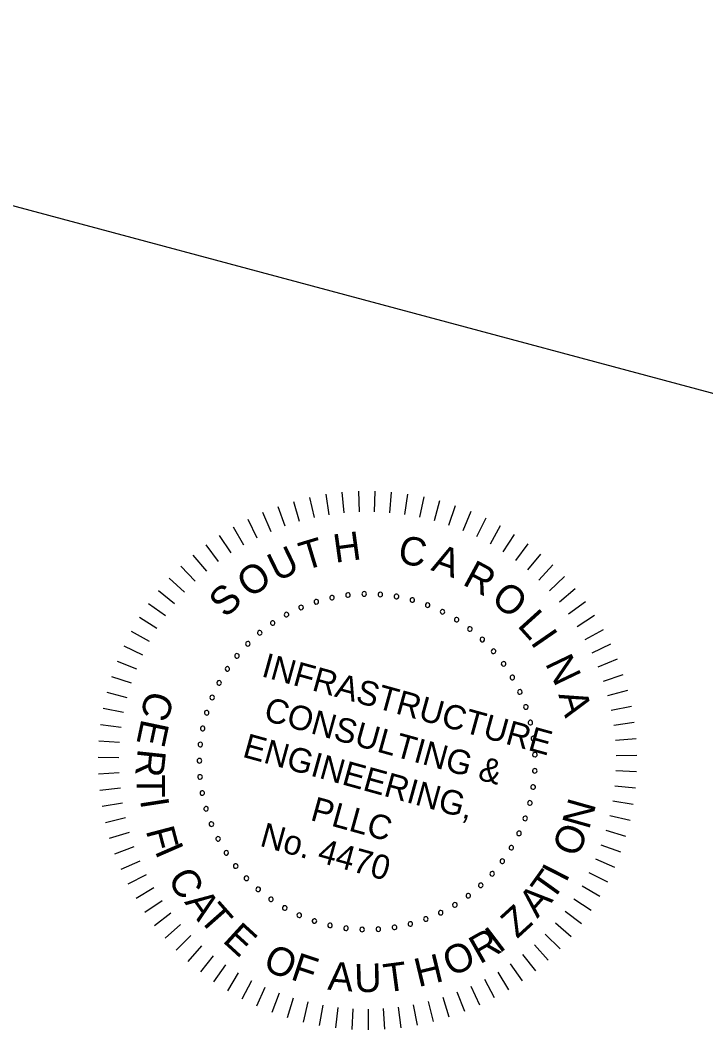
# Model space of a CAD drawing. Extents: x 1970764 to 1971371, y 795839 to 796297.
# Drawn here: x 1971137.24 to 1971168.84, y 795891.27 to 795937.8 of the extents above; entities that cross this region are included whole.
import ezdxf

# ---------------------------------------------------------------- set-up
doc = ezdxf.new("R2010")
doc.units = 0
doc.layers.add('BR_BORDER LINES', color=7, linetype='Continuous')
doc.layers.add('BR_TEXT', color=7, linetype='Continuous')

msp = doc.modelspace()

# ---------------------------------------------------------------- linework, layer by layer
at = {"layer": 'BR_BORDER LINES'}
msp.add_line((1971104.945, 795937.803), (1971182.685, 795916.993), dxfattribs=at)
at = {"layer": 'BR_TEXT'}
for p, q in [((1971150.574, 795915.812), (1971150.781, 795914.879)), ((1971151.318, 795915.952), (1971151.468, 795915.009)), ((1971152.07, 795916.047), (1971152.162, 795915.096)), ((1971152.825, 795916.096), (1971152.859, 795915.141)), ((1971153.583, 795916.098), (1971153.558, 795915.144)), ((1971154.339, 795916.055), (1971154.256, 795915.103)), ((1971155.091, 795915.965), (1971154.95, 795915.021)), ((1971155.836, 795915.83), (1971155.638, 795914.896)), ((1971149.119, 795915.396), (1971149.437, 795914.496)), ((1971149.84, 795915.626), (1971150.103, 795914.708)), ((1971156.571, 795915.65), (1971156.317, 795914.729)), ((1971157.294, 795915.425), (1971156.984, 795914.521)), ((1971148.412, 795915.123), (1971148.785, 795914.244)), ((1971158.002, 795915.156), (1971157.638, 795914.273)), ((1971158.693, 795914.845), (1971158.275, 795913.986)), ((1971147.057, 795914.449), (1971147.534, 795913.622)), ((1971147.724, 795914.807), (1971148.15, 795913.952)), ((1971159.363, 795914.492), (1971158.893, 795913.66)), ((1971146.412, 795914.052), (1971146.939, 795913.255)), ((1971160.01, 795914.099), (1971159.491, 795913.298)), ((1971145.793, 795913.616), (1971146.367, 795912.853)), ((1971160.632, 795913.668), (1971160.065, 795912.899)), ((1971145.202, 795913.143), (1971145.821, 795912.417)), ((1971161.227, 795913.199), (1971160.614, 795912.466)), ((1971144.64, 795912.635), (1971145.303, 795911.948)), ((1971161.792, 795912.695), (1971161.136, 795912.001)), ((1971144.111, 795912.094), (1971144.814, 795911.448)), ((1971162.325, 795912.157), (1971161.628, 795911.505)), ((1971162.825, 795911.588), (1971162.089, 795910.979)), ((1971143.615, 795911.521), (1971144.357, 795910.919)), ((1971143.155, 795910.919), (1971143.932, 795910.364)), ((1971163.289, 795910.989), (1971162.517, 795910.426)), ((1971142.733, 795910.291), (1971143.543, 795909.784)), ((1971163.715, 795910.363), (1971162.91, 795909.849)), ((1971142.35, 795909.637), (1971143.189, 795909.181)), ((1971164.103, 795909.713), (1971163.268, 795909.248)), ((1971142.008, 795908.962), (1971142.873, 795908.557)), ((1971164.45, 795909.04), (1971163.588, 795908.627)), ((1971164.755, 795908.347), (1971163.87, 795907.987)), ((1971141.707, 795908.267), (1971142.595, 795907.916)), ((1971141.449, 795907.555), (1971142.357, 795907.259)), ((1971165.018, 795907.637), (1971164.113, 795907.332)), ((1971141.235, 795906.828), (1971142.16, 795906.588)), ((1971165.237, 795906.912), (1971164.315, 795906.663)), ((1971141.066, 795906.09), (1971142.004, 795905.907)), ((1971165.411, 795906.175), (1971164.476, 795905.982)), ((1971140.942, 795905.343), (1971141.889, 795905.217)), ((1971165.54, 795905.429), (1971164.595, 795905.293)), ((1971165.623, 795904.676), (1971164.671, 795904.599)), ((1971140.864, 795904.59), (1971141.817, 795904.522)), ((1971140.832, 795903.834), (1971141.787, 795903.823)), ((1971165.661, 795903.92), (1971164.706, 795903.901)), ((1971140.847, 795903.076), (1971141.8, 795903.125)), ((1971165.652, 795903.162), (1971164.697, 795903.202)), ((1971140.907, 795902.322), (1971141.856, 795902.428)), ((1971165.597, 795902.407), (1971164.646, 795902.504)), ((1971141.013, 795901.572), (1971141.954, 795901.736)), ((1971165.496, 795901.657), (1971164.553, 795901.812)), ((1971141.165, 795900.83), (1971142.094, 795901.051)), ((1971165.349, 795900.914), (1971164.418, 795901.126)), ((1971165.157, 795900.181), (1971164.241, 795900.45)), ((1971141.361, 795900.099), (1971142.275, 795900.376)), ((1971141.602, 795899.381), (1971142.498, 795899.713)), ((1971164.921, 795899.462), (1971164.023, 795899.785)), ((1971141.887, 795898.679), (1971142.76, 795899.065)), ((1971164.642, 795898.758), (1971163.765, 795899.136)), ((1971142.213, 795897.995), (1971143.061, 795898.434)), ((1971164.32, 795898.072), (1971163.468, 795898.503)), ((1971142.581, 795897.333), (1971143.4, 795897.823)), ((1971163.958, 795897.408), (1971163.133, 795897.89)), ((1971142.988, 795896.695), (1971143.776, 795897.234)), ((1971163.555, 795896.766), (1971162.761, 795897.298)), ((1971163.114, 795896.151), (1971162.354, 795896.73)), ((1971143.433, 795896.082), (1971144.187, 795896.668)), ((1971143.915, 795895.498), (1971144.632, 795896.129)), ((1971162.636, 795895.563), (1971161.913, 795896.187)), ((1971144.432, 795894.945), (1971145.109, 795895.618)), ((1971162.123, 795895.006), (1971161.44, 795895.673)), ((1971144.981, 795894.423), (1971145.616, 795895.137)), ((1971161.577, 795894.481), (1971160.936, 795895.188)), ((1971145.561, 795893.937), (1971146.151, 795894.688)), ((1971161.001, 795893.99), (1971160.403, 795894.735)), ((1971146.17, 795893.486), (1971146.713, 795894.272)), ((1971159.763, 795893.119), (1971159.261, 795893.931)), ((1971160.395, 795893.536), (1971159.844, 795894.316)), ((1971146.805, 795893.074), (1971147.299, 795893.891)), ((1971147.464, 795892.701), (1971147.908, 795893.546)), ((1971159.106, 795892.741), (1971158.655, 795893.583)), ((1971148.144, 795892.369), (1971148.536, 795893.24)), ((1971148.844, 795892.079), (1971149.182, 795892.972)), ((1971157.731, 795892.109), (1971157.385, 795893)), ((1971158.428, 795892.404), (1971158.029, 795893.272)), ((1971149.56, 795891.832), (1971149.842, 795892.744)), ((1971150.289, 795891.629), (1971150.516, 795892.557)), ((1971156.288, 795891.65), (1971156.053, 795892.576)), ((1971157.017, 795891.858), (1971156.726, 795892.767)), ((1971151.03, 795891.471), (1971151.199, 795892.411)), ((1971151.779, 795891.359), (1971151.891, 795892.307)), ((1971152.533, 795891.292), (1971152.587, 795892.246)), ((1971153.29, 795891.272), (1971153.286, 795892.227)), ((1971154.047, 795891.297), (1971153.984, 795892.25)), ((1971154.801, 795891.369), (1971154.68, 795892.317)), ((1971155.549, 795891.487), (1971155.371, 795892.425))]:
    msp.add_line(p, q, dxfattribs=at)
for centre, start, end in [((1971151.609, 795911.19), 12.2328, 192.2328), ((1971151.609, 795911.19), 192.2328, 12.2328), ((1971152.346, 795911.311), 6.6943, 186.6943), ((1971152.346, 795911.311), 186.6943, 6.6943), ((1971153.092, 795911.361), 1.1559, 181.1559), ((1971153.092, 795911.361), 181.1559, 1.1559), ((1971153.839, 795911.338), 175.6174, 355.6174), ((1971153.839, 795911.338), 355.6174, 175.6174), ((1971154.581, 795911.244), 170.079, 350.079), ((1971154.581, 795911.244), 350.079, 170.079), ((1971155.31, 795911.078), 344.5405, 164.5405), ((1971150.186, 795910.737), 23.3097, 203.3097), ((1971150.186, 795910.737), 203.3097, 23.3097), ((1971150.887, 795910.998), 17.7713, 197.7713), ((1971150.887, 795910.998), 197.7713, 17.7713), ((1971155.31, 795911.078), 164.5405, 344.5405), ((1971156.019, 795910.843), 159.002, 339.002), ((1971156.019, 795910.843), 339.002, 159.002), ((1971149.514, 795910.409), 28.8482, 208.8482), ((1971149.514, 795910.409), 208.8482, 28.8482), ((1971156.703, 795910.54), 153.4636, 333.4636), ((1971156.703, 795910.54), 333.4636, 153.4636), ((1971157.354, 795910.173), 147.9251, 327.9251), ((1971157.354, 795910.173), 327.9251, 147.9251), ((1971148.877, 795910.019), 34.3866, 214.3866), ((1971148.877, 795910.019), 214.3866, 34.3866), ((1971157.966, 795909.745), 142.3866, 322.3866), ((1971157.966, 795909.745), 322.3866, 142.3866), ((1971148.28, 795909.569), 39.9251, 219.9251), ((1971148.28, 795909.569), 219.9251, 39.9251), ((1971158.535, 795909.259), 136.8482, 316.8482), ((1971158.535, 795909.259), 316.8482, 136.8482), ((1971147.73, 795909.063), 45.4636, 225.4636), ((1971147.73, 795909.063), 225.4636, 45.4636), ((1971159.054, 795908.721), 131.3097, 311.3097), ((1971159.054, 795908.721), 311.3097, 131.3097), ((1971147.231, 795908.506), 51.002, 231.002), ((1971147.231, 795908.506), 231.002, 51.002), ((1971146.788, 795907.904), 56.5405, 236.5405), ((1971146.788, 795907.904), 236.5405, 56.5405), ((1971159.518, 795908.136), 125.7713, 305.7713), ((1971159.518, 795908.136), 305.7713, 125.7713), ((1971159.924, 795907.508), 120.2328, 300.2328), ((1971159.924, 795907.508), 300.2328, 120.2328), ((1971146.405, 795907.262), 62.079, 242.079), ((1971146.405, 795907.262), 242.079, 62.079), ((1971160.267, 795906.844), 114.6943, 294.6943), ((1971160.267, 795906.844), 294.6943, 114.6943), ((1971146.086, 795906.586), 67.6174, 247.6174), ((1971146.086, 795906.586), 247.6174, 67.6174), ((1971160.545, 795906.15), 109.1559, 289.1559), ((1971160.545, 795906.15), 289.1559, 109.1559), ((1971145.834, 795905.883), 73.1559, 253.1559), ((1971145.834, 795905.883), 253.1559, 73.1559), ((1971160.755, 795905.433), 283.6174, 103.6174), ((1971145.651, 795905.158), 78.6943, 258.6943), ((1971145.651, 795905.158), 258.6943, 78.6943), ((1971160.755, 795905.433), 103.6174, 283.6174), ((1971160.894, 795904.698), 98.079, 278.079), ((1971160.894, 795904.698), 278.079, 98.079), ((1971145.538, 795904.419), 84.2328, 264.2328), ((1971145.538, 795904.419), 264.2328, 84.2328), ((1971145.498, 795903.673), 89.7713, 269.7713), ((1971145.498, 795903.673), 269.7713, 89.7713), ((1971160.962, 795903.954), 92.5405, 272.5405), ((1971160.962, 795903.954), 272.5405, 92.5405), ((1971160.957, 795903.207), 87.002, 267.002), ((1971160.957, 795903.207), 267.002, 87.002), ((1971145.529, 795902.926), 95.3097, 275.3097), ((1971145.529, 795902.926), 275.3097, 95.3097), ((1971145.633, 795902.186), 100.8482, 280.8482), ((1971145.633, 795902.186), 280.8482, 100.8482), ((1971160.88, 795902.463), 81.4636, 261.4636), ((1971160.88, 795902.463), 261.4636, 81.4636), ((1971160.732, 795901.73), 75.9251, 255.9251), ((1971160.732, 795901.73), 255.9251, 75.9251), ((1971145.807, 795901.459), 106.3866, 286.3866), ((1971145.807, 795901.459), 286.3866, 106.3866), ((1971160.514, 795901.015), 70.3866, 250.3866), ((1971160.514, 795901.015), 250.3866, 70.3866), ((1971146.051, 795900.752), 111.9251, 291.9251), ((1971146.051, 795900.752), 291.9251, 111.9251), ((1971160.228, 795900.325), 64.8482, 244.8482), ((1971160.228, 795900.325), 244.8482, 64.8482), ((1971146.362, 795900.073), 117.4636, 297.4636), ((1971146.362, 795900.073), 297.4636, 117.4636), ((1971146.737, 795899.426), 123.002, 303.002), ((1971146.737, 795899.426), 303.002, 123.002), ((1971159.877, 795899.665), 59.3097, 239.3097), ((1971159.877, 795899.665), 239.3097, 59.3097), ((1971159.464, 795899.042), 53.7713, 233.7713), ((1971159.464, 795899.042), 233.7713, 53.7713), ((1971147.173, 795898.819), 128.5405, 308.5405), ((1971147.173, 795898.819), 308.5405, 128.5405), ((1971158.992, 795898.462), 48.2328, 228.2328), ((1971147.665, 795898.256), 134.079, 314.079), ((1971147.665, 795898.256), 314.079, 134.079), ((1971158.992, 795898.462), 228.2328, 48.2328), ((1971148.209, 795897.744), 139.6174, 319.6174), ((1971148.209, 795897.744), 319.6174, 139.6174), ((1971158.467, 795897.931), 42.6943, 222.6943), ((1971158.467, 795897.931), 222.6943, 42.6943), ((1971148.801, 795897.287), 145.1559, 325.1559), ((1971148.801, 795897.287), 325.1559, 145.1559), ((1971157.893, 795897.452), 37.1559, 217.1559), ((1971157.893, 795897.452), 217.1559, 37.1559), ((1971149.433, 795896.888), 150.6943, 330.6943), ((1971149.433, 795896.888), 330.6943, 150.6943), ((1971156.62, 795896.672), 26.079, 206.079), ((1971156.62, 795896.672), 206.079, 26.079), ((1971157.275, 795897.031), 31.6174, 211.6174), ((1971157.275, 795897.031), 211.6174, 31.6174), ((1971150.101, 795896.553), 156.2328, 336.2328), ((1971150.101, 795896.553), 336.2328, 156.2328), ((1971150.799, 795896.284), 161.7713, 341.7713), ((1971150.799, 795896.284), 341.7713, 161.7713), ((1971155.22, 795896.151), 15.002, 195.002), ((1971155.933, 795896.377), 20.5405, 200.5405), ((1971155.933, 795896.377), 200.5405, 20.5405), ((1971151.519, 795896.083), 167.3097, 347.3097), ((1971151.519, 795896.083), 347.3097, 167.3097), ((1971152.255, 795895.953), 172.8482, 352.8482), ((1971152.255, 795895.953), 352.8482, 172.8482), ((1971153, 795895.894), 358.3866, 178.3866), ((1971153, 795895.894), 178.3866, 358.3866), ((1971153.747, 795895.908), 3.9251, 183.9251), ((1971153.747, 795895.908), 183.9251, 3.9251), ((1971154.49, 795895.994), 9.4636, 189.4636), ((1971154.49, 795895.994), 189.4636, 9.4636), ((1971155.22, 795896.151), 195.002, 15.002)]:
    msp.add_arc(centre, 0.105, start, end, dxfattribs=at)

# ---------------------------------------------------------------- texts
for s, height, rotation, p in [('T', 1.308, 16.8319, (1971150.343, 795912.431)), ('H', 1.308, 7.8018, (1971151.757, 795912.792)), ('C', 1.308, 349.7418, (1971154.598, 795912.799)), ('U', 1.308, 25.8619, (1971149.063, 795911.902)), ('A', 1.308, 340.7118, (1971156.131, 795912.465)), ('O', 1.308, 34.8919, (1971147.817, 795911.133)), ('R', 1.308, 331.6817, (1971157.576, 795911.815)), ('S', 1.308, 43.9219, (1971146.711, 795910.215)), ('O', 1.308, 322.6517, (1971158.877, 795911.004)), ('L', 1.308, 312.1217, (1971160.113, 795909.889)), ('I', 1.308, 304.5917, (1971160.728, 795909.138)), ('INFRASTRUCTURE', 1.12157, 344.5405, (1971148.311, 795907.574)), ('N', 1.308, 295.5616, (1971161.412, 795908.166)), ('C', 1.308, 252.0387, (1971143.128, 795906.983)), ('CONSULTING &', 1.12157, 344.5405, (1971148.411, 795905.55)), ('A', 1.308, 286.5316, (1971162.035, 795906.719)), ('E', 1.308, 258.0387, (1971142.837, 795905.639)), ('ENGINEERING,', 1.12157, 344.5405, (1971147.438, 795903.863)), ('R', 1.308, 264.0387, (1971142.664, 795904.252)), ('T', 1.308, 270.0387, (1971142.61, 795903.043)), ('I', 1.308, 278.7849, (1971142.757, 795901.869)), ('PLLC', 1.1216, 344.5405, (1971150.567, 795900.951)), ('N', 1.308, 74.2221, (1971163.454, 795900.459)), ('F', 1.308, 284.7849, (1971143.02, 795900.462)), ('No. 4470', 1.1216, 344.5405, (1971148.236, 795899.76)), ('O', 1.308, 68.2221, (1971162.939, 795899.176)), ('I', 1.308, 293.5405, (1971143.421, 795899.518)), ('C', 1.308, 299.5405, (1971144.009, 795898.272)), ('T', 1.308, 54.409, (1971161.753, 795897.137)), ('I', 1.308, 62.9229, (1971162.387, 795898.015)), ('A', 1.308, 48.409, (1971161.072, 795896.382)), ('A', 1.308, 305.5405, (1971144.784, 795897.155)), ('T', 1.308, 311.5405, (1971145.424, 795896.386)), ('Z', 1.308, 42.409, (1971160.141, 795895.446)), ('E', 1.308, 317.5405, (1971146.522, 795895.35)), ('R', 1.308, 29.5405, (1971158.423, 795894.276)), ('I', 1.308, 37.3475, (1971159.322, 795894.769)), ('O', 1.308, 335.5405, (1971148.363, 795894.099)), ('O', 1.308, 23.5405, (1971157.081, 795893.704)), ('F', 1.308, 341.5405, (1971149.652, 795893.612)), ('A', 1.308, 355.5405, (1971151.383, 795893.123)), ('T', 1.308, 7.5405, (1971154.075, 795892.99)), ('H', 1.308, 13.5405, (1971155.587, 795893.234)), ('U', 1.308, 1.5405, (1971152.651, 795892.993))]:
    msp.add_text(s, height=height, rotation=rotation, dxfattribs=at).set_placement(p)

doc.saveas('drawing.dxf')
